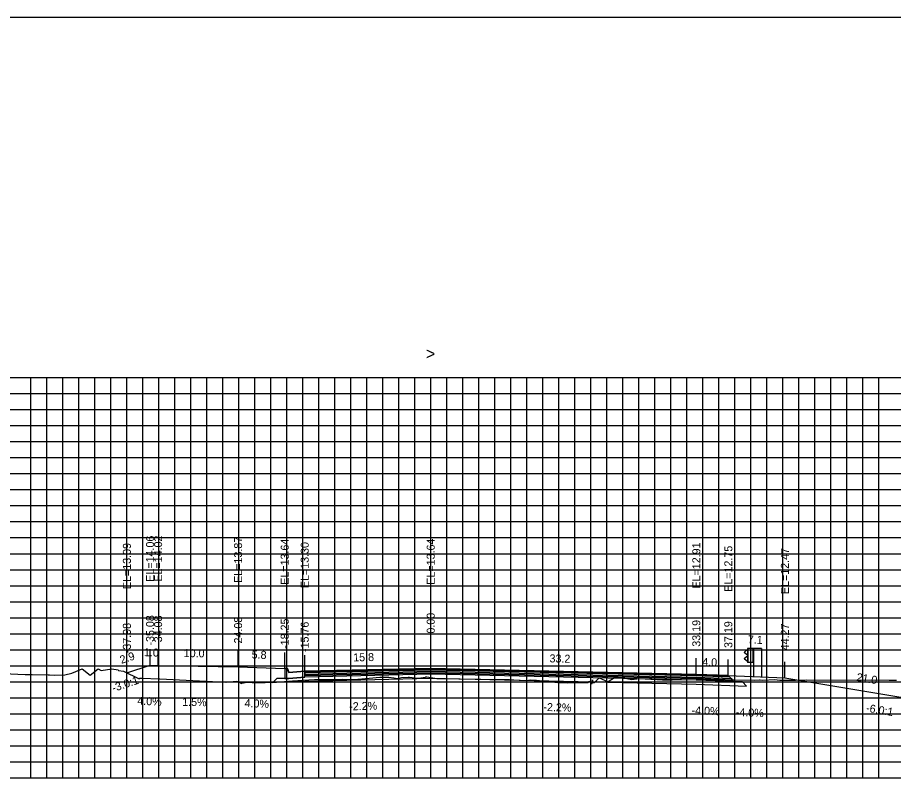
# Model space of a CAD drawing. Extents: x 1797714 to 1804825, y 249015 to 250269.
# Drawn here: x 1802239.4 to 1802348.8, y 250173.2 to 250269.4 of the extents above; entities that cross this region are included whole.
import ezdxf

# ---------------------------------------------------------------- set-up
doc = ezdxf.new("R2010")
doc.units = 0
for name, color, linetype in [('3', 7, 'Continuous'), ('4', 7, 'Continuous'), ('60', 7, 'Continuous'), ('BASE', 7, 'Continuous'), ('CL-CNST', 7, 'Continuous'), ('Level 1', 7, 'Continuous'), ('Level 62', 7, 'Continuous'), ('LOWER BINDER', 7, 'Continuous'), ('M-ROADS', 7, 'Continuous'), ('UPPER BINDER', 7, 'Continuous'), ('WEARING', 7, 'Continuous')]:
    doc.layers.add(name, color=color, linetype=linetype)

msp = doc.modelspace()

# ---------------------------------------------------------------- linework, layer by layer
for p, q in [((1802253.02, 250187.53), (1802253.02, 250189.53)), ((1802255.92, 250188.49), (1802255.92, 250190.49)), ((1802256.92, 250188.45), (1802256.92, 250190.45)), ((1802266.92, 250188.3), (1802266.92, 250190.3)), ((1802272.75, 250188.07), (1802272.75, 250190.07)), ((1802275.25, 250187.73), (1802275.25, 250189.73)), ((1802291, 250188.08), (1802291, 250190.08)), ((1802324.2, 250187.35), (1802324.2, 250189.35)), ((1802328.2, 250187.19), (1802328.2, 250189.19)), ((1802335.27, 250186.9), (1802335.27, 250188.9))]:
    msp.add_line(p, q)
for points in [[(1802141, 250079.43), (1802441, 250079.43), (1802441, 250269.43), (1802141, 250269.43)], [(1802275.25, 250187.73), (1802273.25, 250187.57), (1802273.08, 250188.07), (1802272.75, 250188.07), (1802272.75, 250186.85), (1802273.25, 250186.85), (1802275.25, 250187.01)], [(1802275.25, 250187.73), (1802273.25, 250187.57), (1802273.08, 250188.07), (1802272.75, 250188.07), (1802272.75, 250186.85), (1802273.25, 250186.85), (1802275.25, 250187.01)]]:
    msp.add_lwpolyline(points, close=True)
at = {"layer": '60'}
for p, q in [((1802141, 250174.43), (1802441, 250174.43)), ((1802241, 250174.37), (1802241, 250174.43)), ((1802251, 250174.37), (1802251, 250174.43)), ((1802261, 250174.37), (1802261, 250174.43)), ((1802271, 250174.37), (1802271, 250174.43)), ((1802281, 250174.37), (1802281, 250174.43)), ((1802291, 250174.37), (1802291, 250174.43)), ((1802301, 250174.37), (1802301, 250174.43)), ((1802311, 250174.37), (1802311, 250174.43)), ((1802321, 250174.37), (1802321, 250174.43)), ((1802331, 250174.37), (1802331, 250174.43)), ((1802341, 250174.37), (1802341, 250174.43))]:
    msp.add_line(p, q, dxfattribs=at)
at = {"layer": 'BASE'}
msp.add_lwpolyline([(1802324.2, 250186.13), (1802330.47, 250185.88), (1802329.95, 250186.4), (1802328.95, 250186.44), (1802324.2, 250186.63), (1802291, 250187.36), (1802275.25, 250187.01), (1802273.25, 250186.85), (1802272.75, 250186.85), (1802271.75, 250186.83), (1802271.34, 250186.42), (1802275.25, 250186.51), (1802291, 250186.86)], close=True, dxfattribs=at)
at = {"layer": 'CL-CNST'}
msp.add_lwpolyline([(1802253.02, 250187.53), (1802255.92, 250188.49), (1802256.92, 250188.45), (1802266.92, 250188.3), (1802272.75, 250188.07), (1802273.08, 250188.07), (1802273.25, 250187.57), (1802275.25, 250187.73), (1802291, 250188.08), (1802324.2, 250187.35), (1802328.2, 250187.19), (1802335.27, 250186.9), (1802356.27, 250183.4), (1802360.27, 250183.4), (1802371.89, 250186.31)], dxfattribs=at)
at = {"layer": 'Level 1'}
for p, q in [((1802330.58, 250190.59), (1802330.58, 250188.84)), ((1802332.33, 250190.59), (1802330.58, 250190.59)), ((1802330.63, 250190.59), (1802330.63, 250188.84)), ((1802331.28, 250190.59), (1802331.28, 250188.84)), ((1802331.33, 250190.59), (1802331.33, 250187.06)), ((1802332.33, 250190.59), (1802332.33, 250187.02)), ((1802330.58, 250190.44), (1802330.21, 250190.14)), ((1802330.21, 250190.07), (1802330.58, 250189.78)), ((1802330.58, 250189.64), (1802330.21, 250189.34)), ((1802330.21, 250189.27), (1802330.58, 250188.99)), ((1802331.33, 250188.84), (1802330.58, 250188.84))]:
    msp.add_line(p, q, dxfattribs=at)
for centre in [(1802330.24, 250190.1), (1802330.24, 250189.31)]:
    msp.add_arc(centre, 0.05, 135, 226.6208, dxfattribs=at)
at = {"layer": 'Level 62'}
for p, q in [((1802141, 250224.43), (1802441, 250224.43)), ((1802241, 250174.43), (1802241, 250224.43)), ((1802243, 250174.43), (1802243, 250224.43)), ((1802245, 250174.43), (1802245, 250224.43)), ((1802247, 250174.43), (1802247, 250224.43)), ((1802249, 250174.43), (1802249, 250224.43)), ((1802251, 250174.43), (1802251, 250224.43)), ((1802253, 250174.43), (1802253, 250224.43)), ((1802255, 250174.43), (1802255, 250224.43)), ((1802257, 250174.43), (1802257, 250224.43)), ((1802259, 250174.43), (1802259, 250224.43)), ((1802261, 250174.43), (1802261, 250224.43)), ((1802263, 250174.43), (1802263, 250224.43)), ((1802265, 250174.43), (1802265, 250224.43)), ((1802267, 250174.43), (1802267, 250224.43)), ((1802269, 250174.43), (1802269, 250224.43)), ((1802271, 250174.43), (1802271, 250224.43)), ((1802273, 250174.43), (1802273, 250224.43)), ((1802275, 250174.43), (1802275, 250224.43)), ((1802277, 250174.43), (1802277, 250224.43)), ((1802279, 250174.43), (1802279, 250224.43)), ((1802281, 250174.43), (1802281, 250224.43)), ((1802283, 250174.43), (1802283, 250224.43)), ((1802285, 250174.43), (1802285, 250224.43)), ((1802287, 250174.43), (1802287, 250224.43)), ((1802289, 250174.43), (1802289, 250224.43)), ((1802291, 250174.43), (1802291, 250224.43)), ((1802293, 250174.43), (1802293, 250224.43)), ((1802295, 250174.43), (1802295, 250224.43)), ((1802297, 250174.43), (1802297, 250224.43)), ((1802299, 250174.43), (1802299, 250224.43)), ((1802301, 250174.43), (1802301, 250224.43)), ((1802303, 250174.43), (1802303, 250224.43)), ((1802305, 250174.43), (1802305, 250224.43)), ((1802307, 250174.43), (1802307, 250224.43)), ((1802309, 250174.43), (1802309, 250224.43)), ((1802311, 250174.43), (1802311, 250224.43)), ((1802313, 250174.43), (1802313, 250224.43)), ((1802315, 250174.43), (1802315, 250224.43)), ((1802317, 250174.43), (1802317, 250224.43)), ((1802319, 250174.43), (1802319, 250224.43)), ((1802321, 250174.43), (1802321, 250224.43)), ((1802323, 250174.43), (1802323, 250224.43)), ((1802325, 250174.43), (1802325, 250224.43)), ((1802327, 250174.43), (1802327, 250224.43)), ((1802329, 250174.43), (1802329, 250224.43)), ((1802331, 250174.43), (1802331, 250224.43)), ((1802333, 250174.43), (1802333, 250224.43)), ((1802335, 250174.43), (1802335, 250224.43)), ((1802337, 250174.43), (1802337, 250224.43)), ((1802339, 250174.43), (1802339, 250224.43)), ((1802341, 250174.43), (1802341, 250224.43)), ((1802343, 250174.43), (1802343, 250224.43)), ((1802345, 250174.43), (1802345, 250224.43)), ((1802347, 250174.43), (1802347, 250224.43)), ((1802141, 250222.43), (1802441, 250222.43)), ((1802141, 250220.43), (1802441, 250220.43)), ((1802141, 250218.43), (1802441, 250218.43)), ((1802141, 250216.43), (1802441, 250216.43)), ((1802141, 250214.43), (1802441, 250214.43)), ((1802141, 250212.43), (1802441, 250212.43)), ((1802141, 250210.43), (1802441, 250210.43)), ((1802141, 250208.43), (1802441, 250208.43)), ((1802141, 250206.43), (1802441, 250206.43)), ((1802141, 250204.43), (1802441, 250204.43)), ((1802141, 250202.43), (1802441, 250202.43)), ((1802141, 250200.43), (1802441, 250200.43)), ((1802141, 250198.43), (1802441, 250198.43)), ((1802141, 250196.43), (1802441, 250196.43)), ((1802141, 250194.43), (1802441, 250194.43)), ((1802141, 250192.43), (1802441, 250192.43)), ((1802141, 250190.43), (1802441, 250190.43)), ((1802141, 250188.43), (1802441, 250188.43)), ((1802141, 250186.43), (1802441, 250186.43)), ((1802141, 250184.43), (1802441, 250184.43)), ((1802141, 250182.43), (1802441, 250182.43)), ((1802141, 250180.43), (1802441, 250180.43)), ((1802141, 250178.43), (1802441, 250178.43)), ((1802141, 250176.43), (1802441, 250176.43)), ((1802141, 250174.43), (1802441, 250174.43))]:
    msp.add_line(p, q, dxfattribs=at)
at = {"layer": 'LOWER BINDER'}
for points in [[(1802275.25, 250187.39), (1802291, 250187.74), (1802324.2, 250187.01), (1802328.55, 250186.83), (1802328.74, 250186.64), (1802324.2, 250186.82), (1802291, 250187.55), (1802275.25, 250187.2)], [(1802275.25, 250187.2), (1802291, 250187.55), (1802324.2, 250186.82), (1802328.74, 250186.64), (1802328.95, 250186.44), (1802324.2, 250186.63), (1802291, 250187.36), (1802275.25, 250187.01)]]:
    msp.add_lwpolyline(points, close=True, dxfattribs=at)
at = {"layer": 'M-ROADS'}
msp.add_lwpolyline([(1802237.6, 250187.47), (1802240.3, 250187.34), (1802241.2, 250187.32), (1802243.17, 250187.28), (1802243.36, 250187.28), (1802243.94, 250187.26), (1802245.26, 250187.29), (1802246.13, 250187.49), (1802247.43, 250188.02), (1802248.43, 250187.24), (1802249.43, 250188.02), (1802249.8, 250187.84), (1802251.13, 250188.02), (1802251.95, 250187.92), (1802251.97, 250187.85), (1802252.59, 250187.73), (1802254.57, 250186.8), (1802254.65, 250186.86), (1802254.82, 250186.88), (1802254.83, 250186.89), (1802254.83, 250186.88), (1802254.88, 250186.88), (1802257.1, 250186.8), (1802257.1, 250186.8), (1802257.1, 250186.8), (1802257.11, 250186.8), (1802257.12, 250186.8), (1802265.41, 250186.38), (1802265.43, 250186.39), (1802266.73, 250186.48), (1802267.02, 250186.44), (1802267.33, 250186.21), (1802267.41, 250186.24), (1802267.8, 250186.35), (1802267.86, 250186.36), (1802268.03, 250186.36), (1802268.68, 250186.33), (1802269.48, 250186.32), (1802270.31, 250186.33), (1802270.83, 250186.38), (1802271.23, 250186.34), (1802273.73, 250186.53), (1802274.38, 250186.6), (1802276.47, 250186.71), (1802276.85, 250186.7), (1802277.5, 250186.7), (1802278.92, 250186.69), (1802279.07, 250186.72), (1802279.99, 250186.73), (1802281.45, 250186.69), (1802283.31, 250186.86), (1802284.64, 250186.98), (1802285.75, 250187), (1802286.38, 250186.91), (1802286.79, 250186.84), (1802287.35, 250186.94), (1802288.16, 250186.98), (1802288.36, 250186.98), (1802289, 250186.93), (1802289.47, 250186.86), (1802290.33, 250187.01), (1802290.37, 250187.02), (1802290.4, 250187.03), (1802290.51, 250187.02), (1802291.76, 250186.82), (1802297.28, 250186.73), (1802298.46, 250186.7), (1802298.88, 250186.7), (1802300.85, 250186.69), (1802301.17, 250186.68), (1802301.2, 250186.68), (1802301.3, 250186.67), (1802301.38, 250186.68), (1802302.96, 250186.59), (1802303.44, 250186.68), (1802304.24, 250186.64), (1802306.89, 250186.32), (1802308.1, 250186.29), (1802309.91, 250186.34), (1802310.48, 250186.35), (1802310.67, 250186.33), (1802310.72, 250186.44), (1802310.87, 250186.5), (1802310.97, 250186.39), (1802311.11, 250186.19), (1802311.17, 250186.2), (1802311.17, 250186.2), (1802311.18, 250186.23), (1802311.21, 250186.65), (1802311.26, 250186.31), (1802311.42, 250186.34), (1802311.71, 250186.58), (1802312.06, 250186.92), (1802312.8, 250186.59), (1802313.15, 250186.44), (1802313.17, 250186.44), (1802313.98, 250186.94), (1802314.84, 250186.94), (1802316.13, 250186.7), (1802317.07, 250186.82), (1802319.96, 250186.67), (1802320.42, 250186.67), (1802320.56, 250186.67), (1802321.19, 250186.67), (1802326.44, 250186.69), (1802331.41, 250186.64), (1802332.09, 250186.65), (1802332.16, 250186.65), (1802332.19, 250186.65), (1802332.51, 250186.64), (1802333.99, 250186.71), (1802334.62, 250186.64), (1802335.06, 250186.64), (1802336.59, 250186.64), (1802337.95, 250186.65), (1802348.32, 250186.61), (1802349.22, 250186.62)], dxfattribs=at)
at = {"layer": 'UPPER BINDER'}
msp.add_lwpolyline([(1802275.25, 250187.39), (1802291, 250187.74), (1802324.2, 250187.01), (1802328.55, 250186.83), (1802328.35, 250187.03), (1802324.2, 250187.2), (1802291, 250187.93), (1802275.25, 250187.58)], close=True, dxfattribs=at)
at = {"layer": 'WEARING'}
msp.add_lwpolyline([(1802324.2, 250187.2), (1802328.35, 250187.03), (1802328.2, 250187.19), (1802324.2, 250187.35), (1802291, 250188.08), (1802275.25, 250187.73), (1802275.25, 250187.58), (1802291, 250187.93)], close=True, dxfattribs=at)

# ---------------------------------------------------------------- texts
for s, rotation, p in [('-3.0:1', 18.4349, (1802251.34, 250185.13)), ('-6.0:1', 350.5377, (1802345.36, 250182.69))]:
    msp.add_text(s, height=1, rotation=rotation).set_placement(p)
at = {"layer": '3'}
for s, p in [('EL=14.06', (1802256.42, 250198.92)), ('EL=14.02', (1802257.42, 250198.93)), ('EL=13.87', (1802267.42, 250198.78)), ('EL=13.64', (1802273.25, 250198.54)), ('EL=13.30', (1802275.75, 250198.12)), ('EL=13.64', (1802291.5, 250198.55)), ('EL=12.91', (1802324.7, 250198.07)), ('EL=13.09', (1802253.52, 250198)), ('EL=12.75', (1802328.7, 250197.66)), ('EL=12.47', (1802335.77, 250197.38)), ('0.00', (1802291.5, 250192.44)), ('-35.08', (1802256.42, 250190.95)), ('-34.08', (1802257.42, 250190.91)), ('-24.08', (1802267.42, 250190.76)), ('-18.25', (1802273.25, 250190.53)), ('-15.76', (1802275.75, 250190.14)), ('33.19', (1802324.7, 250190.8)), ('37.19', (1802328.7, 250190.64)), ('-37.98', (1802253.52, 250189.98)), ('44.27', (1802335.77, 250190.35))]:
    msp.add_text(s, height=1, rotation=90, dxfattribs=at).set_placement(p)
at = {"layer": '4'}
for s, rotation, p in [('7.1', 357.7094, (1802330.62, 250191.22)), ('1.0', 357.7094, (1802255.14, 250189.63)), ('2.9', 18.4349, (1802252.34, 250188.65)), ('10.0', 359.1406, (1802260.12, 250189.51)), ('5.8', 357.7094, (1802268.6, 250189.34)), ('15.8', 1.2603, (1802281.32, 250188.96)), ('33.2', 358.7397, (1802305.84, 250188.85)), ('4.0', 357.7094, (1802324.92, 250188.42)), ('21.0', 350.5377, (1802344.16, 250186.54)), ('4.0%', 357.7094, (1802254.31, 250183.55)), ('1.5%', 359.1406, (1802259.93, 250183.41)), ('4.0%', 357.7094, (1802267.72, 250183.27)), ('-2.2%', 1.2603, (1802280.82, 250182.85)), ('-2.2%', 358.7397, (1802305.08, 250182.77)), ('-4.0%', 357.7094, (1802323.59, 250182.37)), ('-4.0%', 357.7094, (1802329.12, 250182.15))]:
    msp.add_text(s, height=1, rotation=rotation, dxfattribs=at).set_placement(p)
at = {"layer": '60'}
msp.add_text('>', height=1.5, dxfattribs=at).set_placement((1802290.39, 250226.68))

doc.saveas('drawing.dxf')
